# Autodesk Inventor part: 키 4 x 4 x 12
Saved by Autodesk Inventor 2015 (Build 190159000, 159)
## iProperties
Created: 2025-08
Part Number: 키 4 x 4 x 12
Material: 일반
Document SubType Name: Modeling
Designer: USER
Density: 1 g/cm^3
Appearance: 기본값
Author: USER
Author: jhkim
Description: 키 및 해당 키홈
Creation Date: 2025-08-05
Sending System: Autodesk Inventor 2026
Preprocessor: ST-DEVELOPER v20.1
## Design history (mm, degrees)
node "키 4 x 4 x 121"
body "Solid1"
node "기준1"
